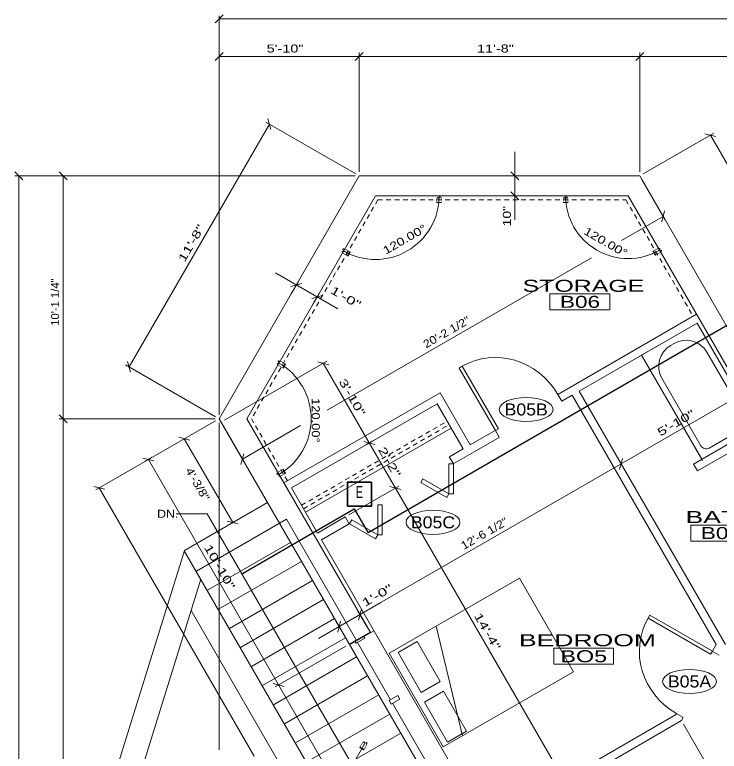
# Model space of a CAD drawing. Extents: x 7 to 126, y 6 to 93.
# Drawn here: x 8.21 to 37.51, y 62.37 to 93.02 of the extents above; entities that cross this region are included whole.
import ezdxf
from ezdxf.enums import TextEntityAlignment as Align

# ---------------------------------------------------------------- set-up
doc = ezdxf.new("R2010")
doc.units = 0
doc.header["$LTSCALE"] = 0.13
doc.linetypes.add('SHORT_DASHED', pattern=[2.7, 1.5, -1.2])
for name, color, linetype, lineweight in [('13', 7, 'Continuous', 13), ('14', 7, 'Continuous', 13), ('15', 7, 'Continuous', 13), ('16', 7, 'Continuous', 13), ('17', 7, 'Continuous', 13), ('24', 7, 'Continuous', 13), ('30', 7, 'Continuous', 13), ('34', 7, 'Continuous', 13), ('35', 7, 'Continuous', 13), ('4', 7, 'Continuous', 13), ('40', 7, 'Continuous', 13), ('42', 7, 'Continuous', 13), ('45', 7, 'Continuous', 13), ('50', 7, 'Continuous', 13), ('53', 7, 'Continuous', 13), ('7', 7, 'Continuous', 13)]:
    doc.layers.add(name, color=color, linetype=linetype, lineweight=lineweight)

msp = doc.modelspace()

# ---------------------------------------------------------------- linework, layer by layer
at = {"layer": '13'}
msp.add_line((19.5074, 72.0229), (22.4164, 66.9845), dxfattribs=at)
at = {"layer": '14'}
msp.add_lwpolyline([(115.8724, 34.3511), (77.539, 34.3511), (75.8724, 37.2379), (59.2057, 37.2379), (57.539, 34.3511), (40.8724, 34.3511), (16.7057, 76.209), (22.539, 86.3127), (34.2057, 86.3127), (44.2057, 68.9922), (60.8724, 68.9922)], dxfattribs=at)
at = {"layer": '15'}
for p, q in [((26.8616, 74.9519), (26.8623, 74.9523)), ((22.1224, 66.8271), (22.9884, 67.3271)), ((35.6958, 63.8865), (35.725, 63.9371))]:
    msp.add_line(p, q, dxfattribs=at)
for points in [[(23.2126, 85.4793), (17.8604, 76.209), (22.999, 67.3088)], [(23.2126, 85.4793), (33.7246, 85.4793), (43.7246, 68.1588), (60.3912, 68.1588), (63.7246, 62.3853)]]:
    msp.add_lwpolyline(points, dxfattribs=at)
at = {"layer": '16'}
for p, q in [((23.1484, 67.3834), (22.138, 66.8)), ((22.7697, 67.0685), (22.728, 67.1407)), ((23.8388, 64.5085), (22.463, 66.8914)), ((23.7847, 64.4772), (24.1455, 64.6856)), ((24.2289, 64.5412), (24.1455, 64.6856)), ((23.868, 64.3329), (23.7847, 64.4772)), ((24.2289, 64.5412), (23.868, 64.3329)), ((23.9221, 64.3641), (25.297, 61.9829))]:
    msp.add_line(p, q, dxfattribs=at)
msp.add_lwpolyline([(22.7697, 67.0685), (22.4089, 66.8602), (22.3672, 66.9324)], dxfattribs=at)
at = {"layer": '17'}
for points in [[(28.1971, 75.7198), (28.3234, 75.7927), (26.8234, 78.3907), (26.6971, 78.3178)], [(26.2694, 74.3353), (26.4516, 74.3353), (26.4517, 73.0853), (26.2694, 73.0853)], [(25.0957, 73.5525), (25.1868, 73.7103), (26.2694, 73.0853), (26.1782, 72.9275)], [(23.3066, 72.623), (23.4889, 72.623), (23.489, 71.373), (23.3067, 71.373)], [(22.133, 71.8402), (22.2241, 71.998), (23.3067, 71.373), (23.2155, 71.2152)], [(37.2244, 66.5356), (37.1515, 66.4093), (34.5527, 67.9079), (34.6256, 68.0343)]]:
    msp.add_lwpolyline(points, close=True, dxfattribs=at)
for centre, major_axis, start_param, end_param in [((28.3234, 75.7927), (-1.5, 2.5981), 4.712389, 6.2831853), ((37.1515, 66.4092), (-2.5988, 1.4987), 6.2831853, 7.8539816)]:
    msp.add_ellipse(centre, major_axis=major_axis, ratio=0.951389, start_param=start_param, end_param=end_param, dxfattribs=at)
at = {"layer": '24', "linetype": 'SHORT_DASHED'}
for p in [(23.3088, 85.3127), (19.5494, 73.6169)]:
    msp.add_line(p, (18.0529, 76.2091), dxfattribs=at)
at = {"layer": '24'}
for p, q in [((36.5897, 80.1835), (43.423, 68.3478)), ((19.7161, 73.3283), (20.7994, 71.4519)), ((27.7994, 59.3275), (20.9661, 71.1632))]:
    msp.add_line(p, q, dxfattribs=at)
at = {"layer": '24', "linetype": 'SHORT_DASHED'}
msp.add_lwpolyline([(23.3088, 85.3127), (33.6283, 85.3127), (36.4184, 80.4802)], dxfattribs=at)
at = {"layer": '30'}
for p, q in [((34.2808, 78.8504), (36.5902, 80.1838)), ((35.4884, 79.259), (35.6327, 79.3423)), ((36.7809, 74.5204), (34.2808, 78.8504)), ((36.8174, 74.4572), (34.3173, 78.7873)), ((36.9987, 78.9763), (38.6238, 76.1617)), ((36.7474, 75.0784), (35.1224, 77.8929)), ((38.5323, 75.8202), (37.0889, 74.9869))]:
    msp.add_line(p, q, dxfattribs=at)
for centre, radius, start, end in [((36.1327, 78.4763), 1, 30.00067, 120.00067), ((35.9884, 78.3929), 1, 120.00068, 210.00068), ((36.9639, 75.2034), 0.25, 210.00068, 300.00068)]:
    msp.add_arc(centre, radius, start, end, dxfattribs=at)
at = {"layer": '34'}
msp.add_line((26.8269, 63.0131), (25.7316, 67.5768), dxfattribs=at)
for points in [[(29.1957, 69.5768), (31.4457, 65.6797), (26.033, 62.5547), (23.783, 66.4518)], [(24.155, 66.4742), (25.1134, 64.8143), (25.9072, 65.2726), (24.9489, 66.9325)], [(25.2495, 64.4118), (26.2079, 62.7519), (27.0017, 63.2102), (26.0434, 64.8701)]]:
    msp.add_lwpolyline(points, close=True, dxfattribs=at)
at = {"layer": '35', "linetype": 'SHORT_DASHED'}
for p, q in [((20.1327, 72.6066), (26.1949, 76.1066)), ((20.2161, 72.4622), (26.2782, 75.9622))]:
    msp.add_line(p, q, dxfattribs=at)
at = {"layer": '35'}
msp.add_line((20.2994, 72.3179), (26.3616, 75.8179), dxfattribs=at)
at = {"layer": '4', "linetype": 'SHORT_DASHED'}
msp.add_line((18.1354, 76.066), (18.15, 76.0408), dxfattribs=at)
at = {"layer": '4'}
for p, q in [((15.2674, 70.7296), (18.7198, 72.7229)), ((15.7674, 69.8636), (19.5074, 72.0229)), ((16.2257, 69.0697), (19.6782, 71.063)), ((15.2674, 70.7296), (8.5387, 49.0213)), ((37.9856, 31.3511), (15.2614, 70.7105)), ((16.684, 68.2759), (20.1365, 70.2692)), ((15.9427, 69.5306), (9.6233, 49.1428)), ((17.1424, 67.482), (20.5948, 69.4753)), ((17.6007, 66.6882), (21.0532, 68.6814)), ((37.4082, 30.3511), (15.5393, 68.2293)), ((18.059, 65.8943), (21.5115, 67.8876)), ((18.5174, 65.1005), (21.9698, 67.0937)), ((18.9757, 64.3066), (22.4282, 66.2999)), ((19.434, 63.5127), (22.8865, 65.506)), ((19.8924, 62.7189), (23.3448, 64.7122)), ((20.3507, 61.925), (23.8031, 63.9183)), ((20.809, 61.1312), (24.2615, 63.1244))]:
    msp.add_line(p, q, dxfattribs=at)
at = {"layer": '40', "lineweight": 25}
msp.add_line((47.0263, 85.4148), (22.9019, 71.4604), dxfattribs=at)
at = {"layer": '40', "lineweight": 35}
msp.add_lwpolyline([(22.0417, 72.5625), (23.0417, 72.5625), (23.0417, 73.5625), (22.0417, 73.5625)], close=True, dxfattribs=at)
at = {"layer": '40', "lineweight": 25}
msp.add_lwpolyline([(17.6771, 69.7708), (22.3273, 72.4556), (22.9019, 71.4604)], dxfattribs=at)
at = {"layer": '42'}
for centre in [(29.4807, 76.5927), (25.6042, 71.8958), (36.2739, 65.2735)]:
    msp.add_ellipse(centre, major_axis=(1.1204, 0), ratio=0.446291, dxfattribs=at)
at = {"layer": '45'}
for points in [[(30.4688, 80.7356), (32.9539, 80.7356), (32.9539, 81.4062), (30.4688, 81.4062)], [(36.3283, 71.1124), (38.8135, 71.1124), (38.8135, 71.783), (36.3283, 71.783)], [(30.625, 65.9862), (33.1102, 65.9862), (33.1102, 66.6569), (30.625, 66.6569)]]:
    msp.add_lwpolyline(points, close=True, dxfattribs=at)
at = {"layer": '50'}
for p, q in [((16.539, 92.6875), (16.8724, 93.0208)), ((16.7057, 76.3757), (16.7057, 92.9792)), ((121.0473, 92.8542), (16.7057, 92.8542)), ((16.7057, 92.8125), (16.7057, 91.1146)), ((16.7057, 92.8125), (16.7057, 92.6875)), ((16.539, 91.1146), (16.8724, 91.4479)), ((22.7057, 91.4479), (22.3724, 91.1146)), ((22.3724, 91.1146), (22.7057, 91.4479)), ((22.539, 86.4793), (22.539, 91.4479)), ((34.3724, 91.4479), (34.039, 91.1146)), ((34.039, 91.1146), (34.3724, 91.4479)), ((34.2057, 86.4793), (34.2057, 91.4479)), ((16.7057, 91.2812), (22.539, 91.2812)), ((22.539, 91.2812), (34.2057, 91.2812)), ((34.2057, 91.2812), (44.2057, 91.2812)), ((18.7381, 88.6996), (18.8601, 88.2443)), ((12.9657, 78.3683), (18.7991, 88.4719)), ((22.3947, 86.396), (18.6547, 88.5553)), ((34.35, 86.396), (37.2852, 88.0906)), ((36.9132, 88.0683), (37.3685, 87.9463)), ((37.1408, 88.0073), (44.8297, 74.6898)), ((29.0104, 84.4793), (29.0104, 87.3127)), ((8.2083, 86.4793), (8.5417, 86.146)), ((10.0521, 86.4793), (10.3854, 86.146)), ((29.1771, 86.146), (28.8438, 86.4793)), ((22.3724, 86.3127), (8.2083, 86.3127)), ((8.375, 86.3127), (8.375, 34.3511)), ((8.375, 86.3127), (10.3854, 86.3127)), ((10.2188, 86.3127), (10.2188, 76.209)), ((28.539, 86.3127), (29.1771, 86.3127)), ((34.289, 86.1683), (35.2612, 84.4845)), ((28.8438, 85.646), (29.1771, 85.3127)), ((28.6353, 85.4793), (29.1771, 85.4793)), ((35.1778, 84.6289), (33.4502, 83.6314)), ((35.2388, 84.8565), (35.1168, 84.4012)), ((21.2062, 76.5624), (32.2015, 82.9105)), ((21.6525, 80.7771), (19.0544, 82.2771)), ((19.7057, 81.4052), (20.0038, 81.9214)), ((20.1481, 81.8381), (19.6928, 81.7161)), ((20.5588, 81.2161), (21.0141, 81.3381)), ((20.6198, 80.9885), (20.8698, 81.4214)), ((13.0267, 78.1406), (12.9047, 78.596)), ((16.9334, 76.148), (21.183, 78.6016)), ((20.8109, 78.5792), (21.2663, 78.4572)), ((21.0386, 78.5182), (22.9553, 75.1984)), ((16.5614, 76.2924), (12.8214, 78.4516)), ((33.4271, 74.3278), (38.479, 77.2445)), ((10.3854, 76.0424), (10.0521, 76.3757)), ((10.0521, 76.3757), (10.3854, 76.0424)), ((16.539, 76.209), (10.0521, 76.209)), ((10.2188, 76.209), (10.2188, 58.3021)), ((16.5614, 76.1257), (11.5767, 73.2478)), ((16.7057, 76.0424), (16.7057, 62.4271)), ((16.789, 76.0647), (17.7612, 74.3809)), ((22.4553, 76.0645), (24.5386, 72.456)), ((17.6778, 74.5252), (20.098, 75.9225)), ((14.7322, 75.0696), (15.4061, 75.4587)), ((15.0341, 75.4364), (15.4895, 75.3144)), ((15.2618, 75.3754), (17.2749, 71.8887)), ((23.183, 75.1374), (22.7276, 75.2594)), ((23.183, 75.1374), (22.7276, 75.2594)), ((23.183, 75.1374), (22.7276, 75.2594)), ((22.9553, 75.1984), (22.811, 75.1151)), ((22.8915, 75.1616), (23.0996, 75.2818)), ((13.5378, 74.5725), (13.9932, 74.4505)), ((13.9247, 74.6034), (13.6211, 74.4282)), ((13.7655, 74.5115), (19.1822, 65.1296)), ((17.6168, 74.2976), (17.7388, 74.7529)), ((33.287, 74.5706), (33.5105, 74.1835)), ((33.4881, 74.5555), (33.3661, 74.1001)), ((33.3661, 74.1002), (33.4881, 74.5555)), ((22.5667, 68.0575), (33.4271, 74.3278)), ((11.4934, 73.3922), (11.9488, 73.2702)), ((11.7211, 73.3312), (18.1721, 62.1578)), ((22.0984, 72.2019), (24.183, 73.4054)), ((23.8077, 73.3888), (24.263, 73.2668)), ((23.811, 73.3831), (24.2663, 73.2611)), ((23.811, 73.3831), (24.2663, 73.2611)), ((24.0386, 73.3221), (31.2053, 60.909)), ((16.7453, 71.5829), (17.4192, 71.972)), ((17.5026, 71.8277), (17.0472, 71.9497)), ((20.8357, 67.0581), (23.4327, 68.5575)), ((22.9156, 67.4531), (22.4834, 68.2019)), ((22.5057, 67.8299), (22.6277, 68.2852)), ((22.5057, 67.8299), (22.6277, 68.2852)), ((21.5948, 67.7433), (21.785, 67.4138)), ((21.7627, 67.7858), (21.6407, 67.3305)), ((21.978, 66.7438), (19.0378, 65.0462)), ((19.4098, 65.0686), (18.9545, 65.1906)), ((18.9545, 65.1906), (19.4098, 65.0686)), ((19.1822, 65.1296), (24.1822, 56.4693)), ((36.0231, 63.4981), (38.2368, 59.6639))]:
    msp.add_line(p, q, dxfattribs=at)
for points in [[(23.7917, 59.1146), (16.2078, 72.2502), (14.9271, 72.2502)], [(22.7708, 62.6979), (19.2859, 56.6618), (17.1667, 56.6618)]]:
    msp.add_lwpolyline(points, dxfattribs=at)
for centre, radius, start, end in [((23.2126, 85.4793), 2.6448, 239.99995, 0), ((33.7246, 85.4793), 2.6063, 180, 300.00001), ((17.8604, 76.209), 2.6761, 300.00021, 59.99994)]:
    msp.add_arc(centre, radius, start, end, dxfattribs=at)
at = {"layer": '53'}
for p, q in [((36.5673, 80.5555), (30.7938, 77.2222)), ((36.5902, 80.1838), (31.6822, 77.3502)), ((19.4051, 73.5336), (25.9003, 77.2836)), ((27.1503, 75.1186), (25.9003, 77.2836)), ((31.6822, 77.3502), (37.7681, 66.8092)), ((30.9605, 76.9335), (30.7952, 77.2197)), ((31.3935, 77.1835), (30.9605, 76.9335)), ((31.3935, 77.1835), (37.3832, 66.8091)), ((19.7161, 73.3283), (25.7782, 76.8283)), ((26.8616, 74.9519), (25.7782, 76.8283)), ((27.1503, 75.1186), (28.1884, 75.7179)), ((28.3624, 75.4335), (28.1971, 75.7198)), ((36.4378, 74.3223), (39.0902, 75.8537)), ((27.3169, 74.8299), (28.3551, 75.4293)), ((36.6045, 74.0337), (39.2569, 75.565)), ((26.8616, 74.9519), (26.294, 74.6242)), ((27.3169, 74.8299), (26.4426, 74.3251)), ((26.4508, 74.3299), (26.2809, 74.6244)), ((36.4378, 74.3223), (36.6045, 74.0337)), ((20.7994, 71.4519), (21.9541, 72.1185)), ((22.1208, 71.8299), (21.9541, 72.1185)), ((20.9661, 71.1632), (22.1208, 71.8299)), ((37.3832, 66.8091), (37.2096, 66.5085)), ((37.5097, 66.3647), (37.2197, 66.5322)), ((27.7994, 59.3275), (35.6958, 63.8865)), ((36.0097, 63.7667), (35.7196, 63.9341)), ((35.9398, 63.6425), (36.0129, 63.7691)), ((27.9661, 59.0389), (35.9398, 63.6425))]:
    msp.add_line(p, q, dxfattribs=at)
at = {"layer": '7'}
msp.add_lwpolyline([(115.8724, 34.3511), (77.539, 34.3511), (75.8724, 37.2379), (59.2057, 37.2379), (57.539, 34.3511), (40.8724, 34.3511), (16.7057, 76.209), (22.539, 86.3127), (34.2057, 86.3127), (44.2057, 68.9922), (60.8724, 68.9922), (64.2057, 63.2187), (65.039, 63.2187), (75.039, 63.2187), (80.039, 71.8789), (96.7057, 71.8789), (98.789, 75.4873), (113.4884, 75.4873), (121.0473, 51.0685)], dxfattribs=at)

# ---------------------------------------------------------------- texts
at = {"layer": '40', "width": 0.7}
msp.add_text('E', height=0.5, dxfattribs=at).set_placement((22.3873, 72.9045))
at = {"layer": '42', "width": 1.1}
for s, p in [('B05B', (29.4807, 76.3427)), ('B05C', (25.6042, 71.6458)), ('B05A', (36.2739, 65.0235))]:
    msp.add_text(s, height=0.5, dxfattribs=at).set_placement(p, align=Align.CENTER)
at = {"layer": '45'}
for s, width, p in [('       STORAGE      ', 1.55, (31.7188, 81.4896)), (' B06 ', 1.4, (31.7187, 80.8229)), ('        BATH        ', 1.65, (37.5783, 71.8664)), (' B07 ', 1.4, (37.5783, 71.1997)), ('       BEDROOM      ', 1.65, (31.875, 66.7402)), (' BO5 ', 1.45, (31.875, 66.0736))]:
    msp.add_text(s, height=0.5, dxfattribs=dict(at, width=width)).set_placement(p, align=Align.CENTER)
at = {"layer": '50'}
for s, width, p in [('5\'-10"', 1.35, (18.6854, 91.4479)), ('11\'-8"', 1.35, (27.4354, 91.4479)), ('DN.', 1.15, (14.1308, 72.0836))]:
    msp.add_text(s, height=0.3333, dxfattribs=dict(at, width=width)).set_placement(p)
for rotation, width, p in [(90, 1.7, (25.9685, 85.4793)), (90, 1.7, (31.2293, 85.4793)), (150, 2.35, (21.8347, 83.3492)), (30, 2.35, (35.1944, 83.1901)), (150, 2.35, (19.1429, 78.687)), (210, 2.35, (19.0318, 73.9235)), (60, 2.35, (22.9312, 62.7535))]:
    msp.add_text('B', height=0.2222, rotation=rotation, dxfattribs=dict(at, width=width)).set_placement(p, align=Align.RIGHT)
for s, rotation, width, p in [('10"', 90, 1.3, (28.8438, 84.2141)), ('11\'-8"', 60, 1.5, (15.2696, 82.692)), ('120.00°', 30, 1.3, (23.6416, 83.029)), ('120.00°', 330, 1.3, (31.8377, 83.9175)), ('10\'-1 1/4"', 90, 1.05, (10.0521, 80.0745)), ('1\'-0"', 330, 1.55, (21.2955, 81.4597)), ('20\'-2 1/2"', 30, 1.15, (25.3171, 79.1282)), ('3\'-10"', 300, 1.5, (21.6728, 77.7531)), ('120.00°', 270, 1.2, (20.5632, 77.063)), ('5\'-10"', 30, 1.5, (35.0583, 75.462)), ('2\'-2"', 300, 1.55, (23.3096, 74.9181)), ('4\'-3/8"', 300, 1.2, (15.2939, 74.0574)), ('12\'-6 1/2"', 30, 1.15, (26.8862, 70.7438)), ('10\'-10"', 300, 1.5, (16.067, 70.8585)), ('1\'-0"', 30, 1.55, (22.772, 68.3685)), ('14\'-4"', 300, 1.5, (27.2978, 68.0104))]:
    msp.add_text(s, height=0.3333, rotation=rotation, dxfattribs=dict(at, width=width)).set_placement(p)

doc.saveas('drawing.dxf')
